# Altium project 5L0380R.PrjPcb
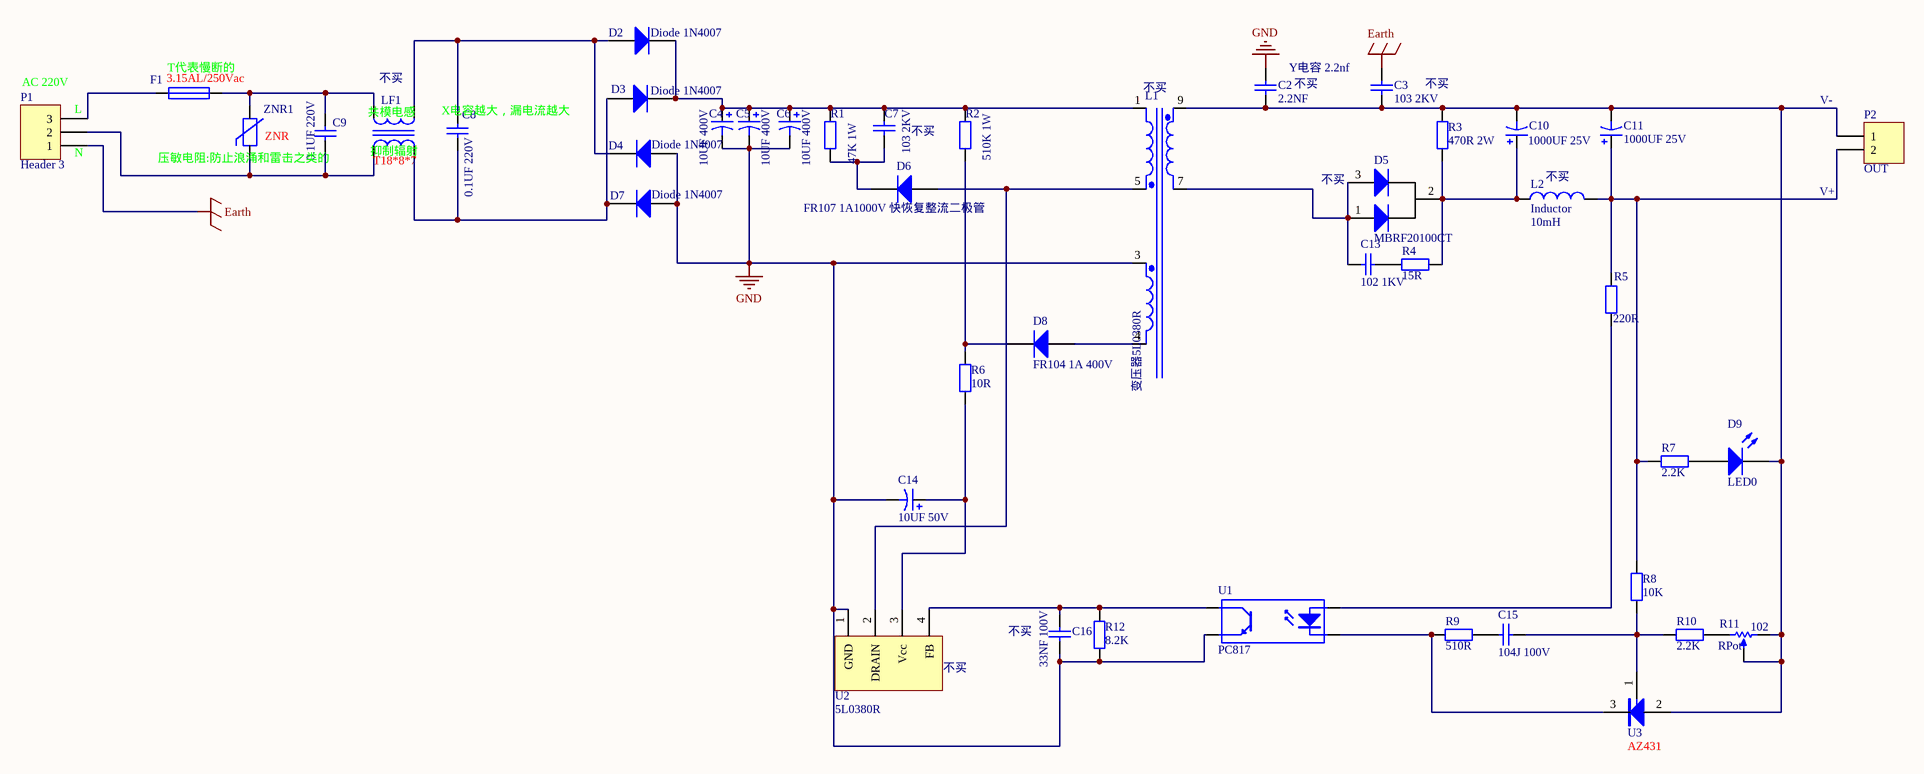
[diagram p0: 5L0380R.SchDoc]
1 sheet, 44 parts. Net scope: global (net labels, ports and power ports of the same name join across sheets).
Board file: 5L0380R.PcbDoc

## Sheet 5L0380R.SchDoc
size A3

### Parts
C2  2.2NF  [Y电容 2.2NF]
C3  103 2KV  [2KV电容]
C4  10UF 400V  [10UF 400v]
C5  10UF 400V  [10UF 400v]
C6  10UF 400V  [10UF 400v]
C7  103 2KV  [2KV电容]
C8  0.1UF 220V  [X电容]
C9  0.1UF 220V  [X电容]
C10  1000UF 25V  [10UF 400v]
C11  1000UF 25V  [10UF 400v]
C13  102 1KV  [2KV电容]
C14  10UF 50V  [25V 100UF]
C15  104J 100V  [100J 100V]
C16  33NF 100V  [33NF 100V电容]
D2  Diode 1N4007  [整流二极管]
D3  Diode 1N4007  [整流二极管]
D4  Diode 1N4007  [整流二极管]
D5  MBRF20100CT  [MBRF20100CT]
D6  FR107 1A1000V 快恢复整流二极管  [DO-35]
D7  Diode 1N4007  [整流二极管]
D8  FR104 1A 400V  [DO-35]
D9  LED0  [插件LED]
F1  3.15AL/250Vac  [熔断丝]
L1  变压器5L0380R  [变压器]
L2  Inductor  value 10mH  [滤波电感]
LF1  T18*8*7  [共模电感]
P1  Header 3  [HDR3X1_D1]
P2  OUT  [HEX2]
R1  47K 1W  [1W电阻]
R2  510K 1W  [1W电阻]
R3  470R 2W  [2W电阻]
R4  15R  [AXIAL-0.4]
R5  220R  [AXIAL-0.4]
R6  10R  [AXIAL-0.4]
R7  2.2K  [AXIAL-0.4]
R8  10K  [AXIAL-0.4]
R9  510R  [AXIAL-0.4]
R10  2.2K  [AXIAL-0.4]
R11  RPot  value 102  [100R滑动变阻器]
R12  8.2K  [AXIAL-0.4]
U1  PC817  [PC817]
U2  5L0380R  [5L0380R]
U3  AZ431  [TL431]
ZNR1  ZNR  [压敏电阻]

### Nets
Earth: C3.2 P1.1
GND: C2.2 C4.2 C5.2 C6.2 C14.2 C16.2 D4.1(A) D7.1(A) L1.3 R12.2 U1.3(E) U2.1(GND)
NetC2_1: C2.1 C3.1 C10.2 C11.2 D9.2(K) L1.9 P2.1 R3.2 R11.2 R11.3 U3.2
NetC4_1: C4.1 C5.1 C6.1 C7.2 D2.2(K) D3.2(K) L1.1 R1.2 R2.2
NetC7_1: C7.1 D6.2(K) R1.1
NetC8_1: C8.1 D3.1(A) D7.2(K) LF1.2
NetC8_2: C8.2 D2.1(A) D4.2(K) LF1.1
NetC9_1: C9.1 LF1.4 P1.2 ZNR1.1
NetC9_2: C9.2 F1.2 LF1.3 ZNR1.2
NetC10_1: C10.1 D5.2 L2.1 R3.1 R4.2
NetC11_1: C11.1 L2.2 P2.2 R5.1 R7.1 R8.2
NetC13_1: C13.1 R4.1
NetC13_2: C13.2 D5.1 D5.3 L1.7
NetC14_1: C14.1 R6.2 U2.3(Vcc)
NetC15_1: C15.1 R9.2
NetC15_2: C15.2 R8.1 R10.1 U3.1
NetC16_1: C16.1 R12.1 U1.4(C) U2.4(FB)
NetD6_1: D6.1(A) L1.5 U2.2(DRAIN)
NetD8_1: D8.1(A) L1.4
NetD8_2: D8.2(K) R2.1 R6.1
NetD9_1: D9.1(A) R7.2
NetF1_1: F1.1 P1.3
NetR5_2: R5.2 U1.1(A)
NetR9_1: R9.1 U1.2(K) U3.3
NetR10_2: R10.2 R11.1

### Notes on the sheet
- (near P1) AC 220V
- (near P1) L
- (near F1) T代表慢断的
- (near LF1) 共模电感
- (near LF1) 不买
- (near C8) X电容越大，漏电流越大
- (near L1) 不买
- Y电容 2.2nf
- (near C2) 不买
- 不买
- (near P2) V-
- (near P1) N
- (near ZNR1) 压敏电阻:防止浪涌和雷击之类的
- (near LF1) 抑制辐射
- (near D5) 不买
- (near L2) 不买
- (near P2) V+
- (near C16) 不买
- (near U2) 不买

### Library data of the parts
C2 C3 C7-C9 C13 C15 C16 = Cap: Capacitor; Value: LC-1206_C
C4-C6 C10 C11 C14 = CAP1: Electronic Capacitor
D2-D4 D7 = Diode 1N4007: 1 Amp General Purpose Rectifier
D5 = MRF20100CT
D6 = Diode 1N914: High Conductance Fast Diode
D8 = Diode 1N4006: 1 Amp General Purpose Rectifier
D9 = LED0: Typical INFRARED GaAs LED
F1 = FUSE
L2 = Inductor: Code_IEC: 1005
LF1 = TRANSFORMER
P1 = Header 3: Header, 3-Pin
P2 = Header 2: Header, 2-Pin
R1-R10 R12 = Res: resistance
R11 = RPot: Potentiometer; Sim Note: Enter the Resistance value and the set point into parameter fields.; Set Position: 0.5
U1 = Optoisolator1: 4-Pin Phototransistor Optocoupler
U3 = 431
